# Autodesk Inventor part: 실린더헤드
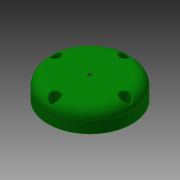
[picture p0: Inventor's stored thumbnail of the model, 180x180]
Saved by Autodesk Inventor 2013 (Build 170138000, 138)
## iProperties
Created: 2016-11
Part Number: 실린더헤드
Material: 알루미늄 6061
Document SubType Name: Modeling
Designer: mduedu
Density: 2.71 g/cm^3
Mass: 235.592 g
Surface Area: 209.258 cm^2
Volume: 86.9344 cm^3
Author: mduedu
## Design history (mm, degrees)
sketch "스케치1"
  geometry: C1 r 42 at (0, 0); 1 further point
  constraints: 1 centre point, 1 coincident
  dimensions: "d0" = 84 diameter of C1
extrude "돌출1" new body sketch "스케치1" distance "d1" = 22; taper "d2" = 0 deg
fillet "모깎기1" dims "d3" = 10
sketch "스케치2"
  geometry: C1 r 30 at (0, 0); 1 further point
  constraints: 1 centre point, 1 coincident
  dimensions: "d4" = 60 diameter of C1
extrude "돌출2" join sketch "스케치2" distance "d5" = 5; taper "d6" = 0 deg
sketch "스케치3"
  geometry: C1 r 25 at (0, 0); 1 further point
  constraints: 1 centre point, 1 coincident
  dimensions: "d7" = 50 diameter of C1
extrude "돌출3" cut sketch "스케치3" distance "d8" = 18; taper "d9" = 0 deg
hole "구멍1" diameter "d12" = 4.134; stored, may be unused: countersink angle "d16" = 90 deg, drill point angle "d18" = 118 deg; dims "d10" = 10, "d11" = 10, "d13" = 6, "d14" = 4, "d15" = 2, "d17" = 8
chamfer "모따기1" distance "d19" = 1; stored, may be unused: second distance "d20" = 2, angle "d21" = 45 deg
fillet "모깎기2" dims "d22" = 3
sketch "스케치4"
  geometry: C1 r 17.5 at (0, 0); 1 further point
  constraints: 1 centre point, 1 coincident
  dimensions: "d23" = 35 diameter of C1
extrude "돌출4" cut sketch "스케치4" distance "d24" = 3; taper "d25" = 0 deg
fillet "모깎기3" dims "d26" = 0.5
sketch "스케치5" dims "d32" = 70
  geometry: C1 r 5 at (0, 35); 3 further points
  constraints: 2 coincident, 2 vertical alignment, 1 centre point, 2 other
  dimensions: "d33" = 10 diameter of C1
extrude "돌출5" cut sketch "스케치5" distance "d34" = 12; taper "d35" = 0 deg
sketch "스케치6" dims "d39" = 70
  geometry: 6 further points
  constraints: 2 vertical alignment, 1 coincident, 7 other
  dimensions: "d42" = 360 deg dimension on point (0, -35) point (0, 0) (derived)
sketch "스케치7"
  geometry: 4 further points
  constraints: 4 other
hole "구멍2" sketch "스케치7" at (0, 70), (-35, 35), (35, 35), (0, 0) diameter "d44" = 5.5; stored, may be unused: countersink angle "d48" = 90 deg, drill point angle "d50" = 0 deg; dims "d45" = 6, "d46" = 4, "d47" = 2, "d49" = 8
fillet "모깎기4" dims "d51" = 0.5
chamfer "모따기2" distance "d54" = 5; stored, may be unused: second distance "d55" = 2, angle "d56" = 30 deg
node "솔리드1"
pattern_circular "원형 패턴1" dims angle "d37" = 360 deg
